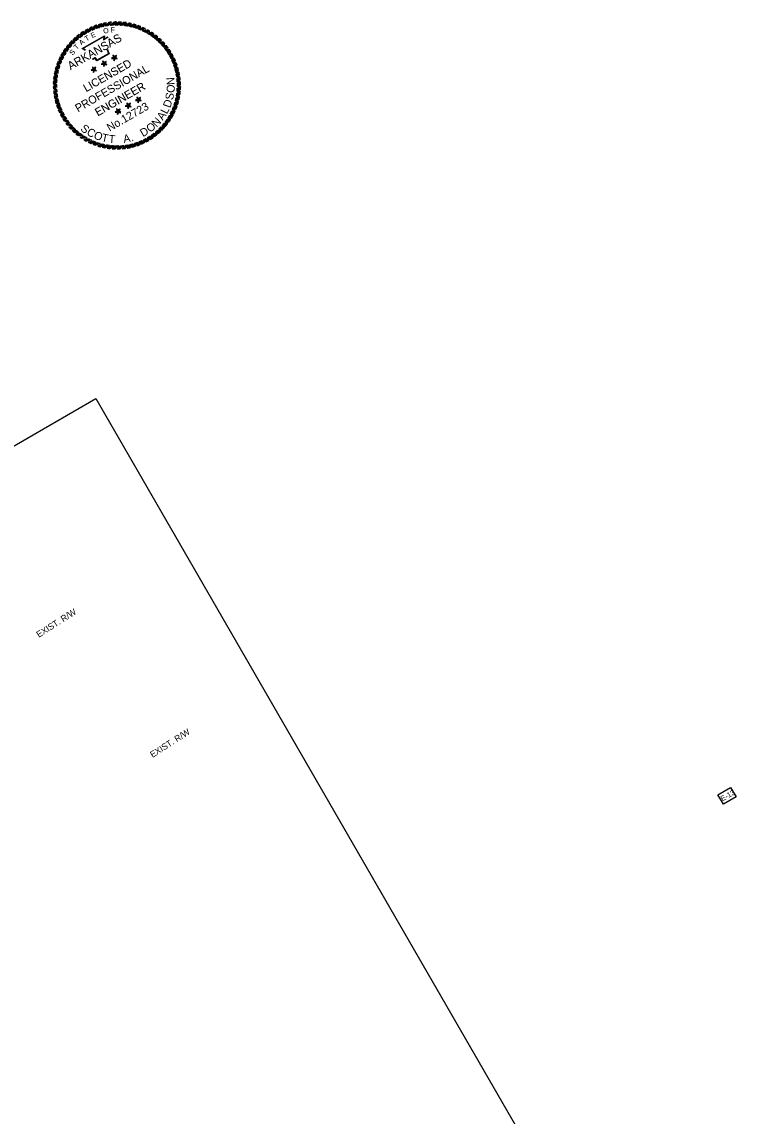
# Model space of a CAD drawing. Extents: x 1293524 to 1295623, y 222963 to 224839.
# Drawn here: x 1294941 to 1295623, y 223794 to 224839 of the extents above; entities that cross this region are included whole.
import ezdxf

# ---------------------------------------------------------------- set-up
doc = ezdxf.new("R2010")
doc.units = 0
for name, color, linetype in [('1', 7, 'Continuous'), ('10Tan10', 7, 'Continuous'), ('Default', 7, 'Continuous'), ('G-No Plot-Border-1', 7, 'Continuous')]:
    doc.layers.add(name, color=color, linetype=linetype)

# ---------------------------------------------------------------- blocks, each defined once
blk = doc.blocks.new('STAR')
at = {"layer": 'Default'}
for p, q in [((0.059, 0.019), (-0.059, 0.019)), ((-0.059, 0.019), (0.036, -0.05)), ((0, 0.062), (-0.037, -0.05)), ((-0.036, -0.05), (0.059, 0.019)), ((-0.008, 0), (0.009, 0)), ((0.036, -0.05), (0, 0.062)), ((0, 0.006), (0, -0.008))]:
    blk.add_line(p, q, dxfattribs=at)
blk = doc.blocks.new('RP')
at = {"layer": 'Default'}
for p, q in [((-0.078, 1.266), (0.003, 1.33)), ((-0.058, 1.267), (0.022, 1.33)), ((-0.038, 1.267), (0.04, 1.329)), ((-0.018, 1.268), (0.059, 1.329))]:
    blk.add_line(p, q, dxfattribs=at)
for radius, start, end in [(1.268, 90.7933, 93.5307), (1.33, 87.4562, 89.8699)]:
    blk.add_arc((0, 0), radius, start, end, dxfattribs=at)

msp = doc.modelspace()

# ---------------------------------------------------------------- linework, layer by layer
at = {"layer": '1'}
msp.add_lwpolyline([(1295606, 224100.5), (1295618.2, 224107.5), (1295623.4, 224098.4), (1295611.3, 224091.4)], close=True, dxfattribs=at)
at = {"layer": 'Default'}
for points in [[(1295001.4, 224811.3), (1294998.6, 224813.3), (1295019.9, 224825.5), (1295019.4, 224822.3), (1295020.8, 224823.1), (1295022, 224823.8), (1295023.3, 224824.4)], [(1295001.4, 224811.4), (1294998.7, 224813.3), (1295020, 224825.5), (1295019.5, 224822.3), (1295020.9, 224823.1), (1295022.1, 224823.8), (1295023.4, 224824.4)], [(1295001.7, 224811.7), (1294999.4, 224813.3), (1295019.5, 224824.8), (1295019, 224821.5), (1295021.1, 224822.8), (1295022.3, 224823.5), (1295023.5, 224824)], [(1295001.6, 224811.6), (1294999.4, 224813.2), (1295019.4, 224824.8), (1295018.9, 224821.5), (1295021, 224822.8), (1295022.2, 224823.5), (1295023.5, 224824.1)], [(1295023.2, 224812), (1295023, 224811.5), (1295023.2, 224811), (1295023.7, 224809.9), (1295024.5, 224808.4), (1295012.7, 224801.5), (1295011.5, 224803.5), (1295011.3, 224804), (1295010.7, 224803.8), (1295009, 224802.9), (1295008.4, 224803.1)], [(1295023.2, 224812), (1295023.1, 224811.5), (1295023.2, 224811), (1295023.7, 224809.8), (1295024.5, 224808.3), (1295012.7, 224801.5), (1295011.5, 224803.5), (1295011.3, 224804), (1295010.7, 224803.8), (1295009, 224802.9), (1295008.5, 224803.2)], [(1295022.8, 224812.2), (1295022.6, 224811.6), (1295022.8, 224810.9), (1295023.3, 224809.7), (1295024, 224808.5), (1295012.8, 224802.1), (1295011.9, 224803.7), (1295011.5, 224804.4), (1295010.6, 224804.2), (1295009, 224803.3), (1295008.6, 224803.5)], [(1295022.9, 224812.1), (1295022.6, 224811.5), (1295022.8, 224810.9), (1295023.3, 224809.6), (1295024, 224808.5), (1295012.8, 224802.1), (1295011.9, 224803.7), (1295011.5, 224804.4), (1295010.6, 224804.2), (1295009, 224803.3), (1295008.6, 224803.5)]]:
    msp.add_lwpolyline(points, dxfattribs=at)
at = {"layer": 'G-No Plot-Border-1'}
msp.add_lwpolyline([(1294045, 222962.9), (1293523.9, 223865.5), (1294561.4, 224464.5), (1294586.2, 224421.6), (1294757.9, 224520.8), (1294765.6, 224507.3), (1294827.6, 224543.1), (1294901.4, 224415.4), (1295011.8, 224479.1), (1295426.7, 223760.5)], close=True, dxfattribs=at)
msp.add_lwpolyline([(1294045, 222962.9), (1293523.9, 223865.5), (1294561.4, 224464.5), (1294586.2, 224421.6), (1294757.9, 224520.8), (1294765.6, 224507.3), (1294827.6, 224543.1), (1294901.4, 224415.4), (1295011.8, 224479.1), (1295426.7, 223760.5)], close=True, dxfattribs=at)
msp.add_lwpolyline([(1294045, 222962.9), (1293523.9, 223865.5), (1294561.4, 224464.5), (1294586.2, 224421.6), (1294757.9, 224520.8), (1294765.6, 224507.3), (1294827.6, 224543.1), (1294901.4, 224415.4), (1295011.8, 224479.1), (1295426.7, 223760.5)], close=True, dxfattribs=at)
msp.add_lwpolyline([(1294045, 222962.9), (1293523.9, 223865.5), (1294561.4, 224464.5), (1294586.2, 224421.6), (1294757.9, 224520.8), (1294765.6, 224507.3), (1294827.6, 224543.1), (1294901.4, 224415.4), (1295011.8, 224479.1), (1295426.7, 223760.5)], close=True, dxfattribs=at)

# ---------------------------------------------------------------- block references
at = {"layer": 'Default'}
for name, p, xscale, yscale, rotation in [('RP', (1295031.9, 224778), 45.58827671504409, 45.58827671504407, 12.000000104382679), ('RP', (1295031.8, 224777.9), 45.58827671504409, 45.58827671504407, 11.804199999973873), ('RP', (1295031.9, 224778), 45.58827671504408, 45.58827671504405, 7.500000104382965), ('RP', (1295031.8, 224777.9), 45.58827671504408, 45.58827671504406, 7.3041999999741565), ('RP', (1295031.9, 224778), 45.58827671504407, 45.58827671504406, 3.000000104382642), ('RP', (1295031.8, 224777.9), 45.58827671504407, 45.58827671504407, 2.804199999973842), ('RP', (1295031.9, 224778), 45.58827671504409, 45.588276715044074, -1.4999998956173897), ('RP', (1295031.8, 224777.9), 45.588276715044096, 45.58827671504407, -1.6958000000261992), ('RP', (1295031.9, 224778), 45.58827671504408, 45.58827671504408, -5.999999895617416), ('RP', (1295031.8, 224777.9), 45.58827671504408, 45.588276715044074, -6.195800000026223), ('RP', (1295031.9, 224778), 45.58827671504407, 45.588276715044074, -10.49999989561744), ('RP', (1295031.8, 224777.9), 45.588276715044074, 45.58827671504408, -10.695800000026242), ('RP', (1295031.9, 224778), 45.58827671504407, 45.58827671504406, -14.999999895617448), ('RP', (1295031.8, 224777.9), 45.58827671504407, 45.58827671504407, -15.19580000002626), ('RP', (1295031.9, 224778), 45.588276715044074, 45.58827671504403, 39.00000010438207), ('RP', (1295031.8, 224777.9), 45.58827671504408, 45.58827671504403, 38.80419999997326), ('RP', (1295031.9, 224778), 45.588276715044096, 45.588276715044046, 34.500000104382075), ('RP', (1295031.8, 224777.9), 45.588276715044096, 45.58827671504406, 34.304199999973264), ('RP', (1295031.9, 224778), 45.588276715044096, 45.588276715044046, 30.00000010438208), ('RP', (1295031.8, 224777.9), 45.58827671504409, 45.588276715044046, 29.804199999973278), ('RP', (1295031.9, 224778), 45.58827671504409, 45.588276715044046, 25.50000010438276), ('RP', (1295031.8, 224777.9), 45.588276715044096, 45.58827671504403, 25.304199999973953), ('RP', (1295031.9, 224778), 45.588276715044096, 45.58827671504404, 21.00000010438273), ('RP', (1295031.8, 224777.9), 45.58827671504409, 45.588276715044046, 20.804199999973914), ('RP', (1295031.9, 224778), 45.588276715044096, 45.58827671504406, 16.50000010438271), ('RP', (1295031.8, 224777.9), 45.58827671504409, 45.58827671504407, 16.304199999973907), ('RP', (1295031.9, 224778), 45.58827671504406, 45.58827671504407, -19.499999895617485), ('RP', (1295031.8, 224777.9), 45.58827671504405, 45.58827671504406, -19.695800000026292), ('RP', (1295031.9, 224778), 45.58827671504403, 45.58827671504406, -23.999999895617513), ('RP', (1295031.8, 224777.9), 45.58827671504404, 45.58827671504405, -24.19580000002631), ('RP', (1295031.9, 224778), 45.58827671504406, 45.58827671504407, -28.499999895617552), ('RP', (1295031.8, 224777.9), 45.58827671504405, 45.58827671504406, -28.69580000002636), ('RP', (1295031.9, 224778), 45.588276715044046, 45.58827671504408, -32.99999989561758), ('RP', (1295031.8, 224777.9), 45.58827671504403, 45.58827671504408, -33.19580000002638), ('RP', (1295031.9, 224778), 45.58827671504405, 45.58827671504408, -37.49999989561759), ('RP', (1295031.8, 224777.9), 45.58827671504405, 45.58827671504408, -37.695800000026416), ('RP', (1295031.9, 224778), 45.588276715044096, 45.58827671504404, 52.50000010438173), ('RP', (1295031.8, 224777.9), 45.58827671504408, 45.58827671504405, 52.30419999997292), ('RP', (1295031.8, 224777.9), 45.58827671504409, 45.588276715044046, 47.80419999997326), ('RP', (1295031.9, 224778), 45.58827671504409, 45.588276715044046, 48.00000010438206), ('RP', (1295031.8, 224777.9), 45.58827671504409, 45.588276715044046, 43.30419999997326), ('RP', (1295031.9, 224778), 45.58827671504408, 45.588276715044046, 43.50000010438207), ('RP', (1295031.9, 224778), 45.58827671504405, 45.58827671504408, -41.99999989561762), ('RP', (1295031.8, 224777.9), 45.588276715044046, 45.58827671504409, -42.19580000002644), ('RP', (1295031.9, 224778), 45.58827671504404, 45.58827671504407, -46.49999989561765), ('RP', (1295031.8, 224777.9), 45.58827671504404, 45.58827671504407, -46.69580000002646), ('RP', (1295031.9, 224778), 45.588276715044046, 45.58827671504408, -50.999999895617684), ('RP', (1295031.8, 224777.9), 45.588276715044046, 45.58827671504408, -51.19580000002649), ('RP', (1295031.8, 224777.9), 45.58827671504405, 45.58827671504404, 61.30419999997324), ('RP', (1295031.9, 224778), 45.58827671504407, 45.58827671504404, 61.50000010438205), ('RP', (1295031.8, 224777.9), 45.58827671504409, 45.58827671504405, 56.804199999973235), ('RP', (1295031.9, 224778), 45.58827671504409, 45.58827671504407, 57.000000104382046), ('STAR', (1295029.4, 224804.5), 45.588276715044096, 45.588276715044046, 30.00000010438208), ('STAR', (1295029.4, 224804.4), 45.58827671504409, 45.588276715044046, 29.804199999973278), ('RP', (1295031.9, 224778), 45.588276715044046, 45.58827671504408, -55.499999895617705), ('RP', (1295031.8, 224777.9), 45.58827671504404, 45.588276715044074, -55.695800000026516), ('RP', (1295031.9, 224778), 45.588276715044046, 45.588276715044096, -59.99999989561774), ('RP', (1295031.8, 224777.9), 45.588276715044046, 45.58827671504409, -60.19580000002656), ('RP', (1295031.9, 224778), 45.58827671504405, 45.58827671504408, -64.49999989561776), ('RP', (1295031.8, 224777.9), 45.588276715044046, 45.58827671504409, -64.69580000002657), ('RP', (1295031.8, 224777.9), 45.58827671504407, 45.58827671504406, 74.80419999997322), ('RP', (1295031.9, 224778), 45.588276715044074, 45.58827671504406, 75.00000010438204), ('RP', (1295031.8, 224777.9), 45.588276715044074, 45.58827671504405, 70.30419999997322), ('RP', (1295031.9, 224778), 45.588276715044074, 45.58827671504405, 70.50000010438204), ('RP', (1295031.8, 224777.9), 45.58827671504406, 45.58827671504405, 65.80419999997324), ('RP', (1295031.9, 224778), 45.588276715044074, 45.58827671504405, 66.00000010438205), ('STAR', (1295009.9, 224793.2), 45.58827671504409, 45.588276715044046, 29.804199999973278), ('STAR', (1295009.9, 224793.2), 45.588276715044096, 45.588276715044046, 30.00000010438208), ('STAR', (1295019.6, 224798.8), 45.58827671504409, 45.588276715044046, 29.804199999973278), ('STAR', (1295019.7, 224798.9), 45.588276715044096, 45.588276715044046, 30.00000010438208), ('RP', (1295031.9, 224778), 45.58827671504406, 45.58827671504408, -68.9999998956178), ('RP', (1295031.8, 224777.9), 45.58827671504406, 45.588276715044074, -69.19580000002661), ('RP', (1295031.9, 224778), 45.58827671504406, 45.588276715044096, -73.49999989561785), ('RP', (1295031.8, 224777.9), 45.58827671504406, 45.588276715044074, -73.69580000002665), ('RP', (1295031.8, 224777.9), 45.588276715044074, 45.58827671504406, 83.80419999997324), ('RP', (1295031.9, 224778), 45.588276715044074, 45.58827671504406, 84.00000010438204), ('RP', (1295031.8, 224777.9), 45.58827671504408, 45.58827671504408, 79.30419999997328), ('RP', (1295031.9, 224778), 45.58827671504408, 45.588276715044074, 79.50000010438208), ('RP', (1295031.9, 224778), 45.58827671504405, 45.588276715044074, -77.99999989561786), ('RP', (1295031.8, 224777.9), 45.588276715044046, 45.58827671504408, -78.19580000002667), ('RP', (1295031.9, 224778), 45.588276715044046, 45.58827671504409, -82.49999989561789), ('RP', (1295031.8, 224777.9), 45.58827671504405, 45.58827671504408, -82.6958000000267), ('RP', (1295031.8, 224777.9), 45.58827671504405, 45.58827671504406, 88.30419999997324), ('RP', (1295031.8, 224777.9), 45.58827671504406, 45.58827671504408, 92.80419999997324), ('RP', (1295031.9, 224778), 45.58827671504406, 45.58827671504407, 88.50000010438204), ('RP', (1295031.9, 224778), 45.58827671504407, 45.58827671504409, 93.00000010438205), ('RP', (1295031.8, 224777.9), 45.588276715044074, 45.58827671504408, -96.19580000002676), ('RP', (1295031.9, 224778), 45.588276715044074, 45.58827671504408, -95.99999989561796), ('RP', (1295031.9, 224778), 45.588276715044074, 45.58827671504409, -86.99999989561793), ('RP', (1295031.8, 224777.9), 45.58827671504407, 45.58827671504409, -87.19580000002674), ('RP', (1295031.8, 224777.9), 45.58827671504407, 45.588276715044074, -91.69580000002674), ('RP', (1295031.9, 224778), 45.58827671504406, 45.58827671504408, -91.49999989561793), ('RP', (1295031.8, 224777.9), 45.58827671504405, 45.58827671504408, 97.30419999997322), ('RP', (1295031.9, 224778), 45.58827671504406, 45.58827671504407, 97.50000010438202), ('RP', (1295031.8, 224777.9), 45.58827671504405, 45.58827671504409, 101.80419999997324), ('RP', (1295031.9, 224778), 45.58827671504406, 45.588276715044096, 102.00000010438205), ('RP', (1295031.8, 224777.9), 45.58827671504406, 45.58827671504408, 106.30419999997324), ('RP', (1295031.9, 224778), 45.58827671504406, 45.588276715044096, 106.50000010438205), ('STAR', (1295052.4, 224764.3), 45.58827671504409, 45.588276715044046, 29.804199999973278), ('STAR', (1295052.5, 224764.4), 45.588276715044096, 45.588276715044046, 30.00000010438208), ('RP', (1295031.8, 224777.9), 45.58827671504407, 45.58827671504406, -105.19580000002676), ('RP', (1295031.9, 224778), 45.588276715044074, 45.58827671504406, -104.99999989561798), ('RP', (1295031.8, 224777.9), 45.588276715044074, 45.58827671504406, -100.69580000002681), ('RP', (1295031.9, 224778), 45.588276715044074, 45.58827671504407, -100.49999989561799), ('RP', (1295031.8, 224777.9), 45.58827671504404, 45.588276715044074, 110.80419999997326), ('RP', (1295031.9, 224778), 45.588276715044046, 45.58827671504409, 111.00000010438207), ('RP', (1295031.8, 224777.9), 45.588276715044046, 45.588276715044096, 115.30419999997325), ('RP', (1295031.9, 224778), 45.58827671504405, 45.58827671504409, 115.50000010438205), ('STAR', (1295032.8, 224753.1), 45.58827671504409, 45.588276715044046, 29.804199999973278), ('STAR', (1295033, 224753.2), 45.588276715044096, 45.588276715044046, 30.00000010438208), ('STAR', (1295042.6, 224758.7), 45.58827671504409, 45.588276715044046, 29.804199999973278), ('STAR', (1295042.8, 224758.8), 45.588276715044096, 45.588276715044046, 30.00000010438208), ('RP', (1295031.9, 224778), 45.588276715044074, 45.58827671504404, -118.49999989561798), ('RP', (1295031.8, 224777.9), 45.58827671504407, 45.58827671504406, -114.19580000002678), ('RP', (1295031.9, 224778), 45.58827671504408, 45.58827671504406, -113.99999989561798), ('RP', (1295031.8, 224777.9), 45.58827671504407, 45.588276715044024, -109.69580000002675), ('RP', (1295031.9, 224778), 45.58827671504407, 45.588276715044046, -109.49999989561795), ('RP', (1295031.8, 224777.9), 45.588276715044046, 45.588276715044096, 119.80419999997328), ('RP', (1295031.9, 224778), 45.58827671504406, 45.5882767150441, 120.00000010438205), ('RP', (1295031.8, 224777.9), 45.58827671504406, 45.58827671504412, 124.30419999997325), ('RP', (1295031.9, 224778), 45.58827671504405, 45.5882767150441, 124.50000010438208), ('RP', (1295031.8, 224777.9), 45.58827671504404, 45.58827671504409, 128.8041999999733), ('RP', (1295031.9, 224778), 45.58827671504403, 45.58827671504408, 129.0000001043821), ('RP', (1295031.8, 224777.9), 45.58827671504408, 45.58827671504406, -127.6958000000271), ('RP', (1295031.9, 224778), 45.58827671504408, 45.58827671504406, -127.4999998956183), ('RP', (1295031.8, 224777.9), 45.588276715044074, 45.58827671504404, -123.1958000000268), ('RP', (1295031.9, 224778), 45.588276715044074, 45.58827671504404, -122.99999989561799), ('RP', (1295031.8, 224777.9), 45.58827671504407, 45.588276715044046, -118.69580000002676), ('RP', (1295031.8, 224777.9), 45.58827671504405, 45.58827671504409, 133.30419999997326), ('RP', (1295031.9, 224778), 45.58827671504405, 45.58827671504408, 133.50000010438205), ('RP', (1295031.8, 224777.9), 45.58827671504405, 45.5882767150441, 137.8041999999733), ('RP', (1295031.9, 224778), 45.58827671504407, 45.588276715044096, 138.00000010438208), ('RP', (1295031.8, 224777.9), 45.588276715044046, 45.58827671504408, 142.3041999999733), ('RP', (1295031.9, 224778), 45.58827671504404, 45.588276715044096, 142.50000010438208), ('RP', (1295031.8, 224777.9), 45.588276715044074, 45.58827671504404, -141.19580000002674), ('RP', (1295031.9, 224778), 45.588276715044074, 45.58827671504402, -140.99999989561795), ('RP', (1295031.8, 224777.9), 45.58827671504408, 45.588276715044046, -136.69580000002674), ('RP', (1295031.9, 224778), 45.58827671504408, 45.58827671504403, -136.49999989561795), ('RP', (1295031.8, 224777.9), 45.58827671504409, 45.588276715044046, -132.19580000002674), ('RP', (1295031.9, 224778), 45.588276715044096, 45.588276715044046, -131.99999989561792), ('RP', (1295031.8, 224777.9), 45.58827671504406, 45.58827671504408, 146.8041999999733), ('RP', (1295031.9, 224778), 45.58827671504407, 45.58827671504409, 147.00000010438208), ('RP', (1295031.8, 224777.9), 45.58827671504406, 45.58827671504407, 151.3041999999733), ('RP', (1295031.9, 224778), 45.58827671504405, 45.588276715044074, 151.50000010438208), ('RP', (1295031.8, 224777.9), 45.588276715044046, 45.58827671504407, 155.8041999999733), ('RP', (1295031.9, 224778), 45.588276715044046, 45.58827671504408, 156.0000001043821), ('RP', (1295031.8, 224777.9), 45.58827671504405, 45.588276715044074, 160.3041999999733), ('RP', (1295031.9, 224778), 45.58827671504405, 45.588276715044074, 160.50000010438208), ('RP', (1295031.8, 224777.9), 45.58827671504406, 45.58827671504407, 164.8041999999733), ('RP', (1295031.9, 224778), 45.58827671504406, 45.588276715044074, 165.0000001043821), ('RP', (1295031.9, 224778), 45.5882767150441, 45.58827671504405, -167.99999989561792), ('RP', (1295031.8, 224777.9), 45.58827671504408, 45.58827671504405, -163.69580000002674), ('RP', (1295031.9, 224778), 45.58827671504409, 45.588276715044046, -163.49999989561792), ('RP', (1295031.8, 224777.9), 45.58827671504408, 45.58827671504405, -159.1958000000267), ('RP', (1295031.9, 224778), 45.58827671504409, 45.588276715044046, -158.99999989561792), ('RP', (1295031.8, 224777.9), 45.588276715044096, 45.588276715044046, -154.6958000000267), ('RP', (1295031.9, 224778), 45.5882767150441, 45.58827671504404, -154.49999989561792), ('RP', (1295031.8, 224777.9), 45.588276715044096, 45.588276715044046, -150.19580000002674), ('RP', (1295031.9, 224778), 45.5882767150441, 45.58827671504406, -149.99999989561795), ('RP', (1295031.8, 224777.9), 45.58827671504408, 45.588276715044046, -145.69580000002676), ('RP', (1295031.9, 224778), 45.588276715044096, 45.58827671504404, -145.49999989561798), ('RP', (1295031.8, 224777.9), 45.588276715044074, 45.58827671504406, 169.30419999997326), ('RP', (1295031.9, 224778), 45.58827671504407, 45.588276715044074, 169.50000010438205), ('RP', (1295031.8, 224777.9), 45.588276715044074, 45.58827671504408, 173.8041999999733), ('RP', (1295031.9, 224778), 45.58827671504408, 45.588276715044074, 174.00000010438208), ('RP', (1295031.8, 224777.9), 45.58827671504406, 45.58827671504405, 178.3041999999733), ('RP', (1295031.9, 224778), 45.58827671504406, 45.58827671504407, 178.50000010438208), ('RP', (1295031.8, 224777.9), 45.58827671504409, 45.588276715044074, -177.1958000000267), ('RP', (1295031.9, 224778), 45.5882767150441, 45.58827671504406, -176.99999989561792), ('RP', (1295031.8, 224777.9), 45.588276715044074, 45.58827671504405, -172.6958000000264), ('RP', (1295031.9, 224778), 45.588276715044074, 45.58827671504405, -172.49999989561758), ('RP', (1295031.8, 224777.9), 45.588276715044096, 45.58827671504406, -168.19580000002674)]:
    msp.add_blockref(name, p, dxfattribs=dict(at, xscale=xscale, yscale=yscale, rotation=rotation))

# ---------------------------------------------------------------- texts
at = {"layer": '1'}
msp.add_text('E-13', height=5, rotation=29.6136, dxfattribs=at).set_placement((1295610.3, 224094))
at = {"layer": '10Tan10'}
for p in [(1294957.3, 224250.3), (1295065.9, 224135.6)]:
    msp.add_text('EXIST. R/W', height=6, rotation=32.6554, dxfattribs=at).set_placement(p)
at = {"layer": 'Default'}
for s, height, rotation, p in [('ARKANSAS', 7.89, 29.8042, (1294987.5, 224792.5)), ('ARKANSAS', 7.89, 30, (1294987.5, 224792.4)), ('E', 4.84, 26.672, (1295008.2, 224823)), ('E', 4.84, 26.4762, (1295008.2, 224823)), ('O', 4.84, 11.2218, (1295019.2, 224827.4)), ('O', 4.84, 11.026, (1295019.3, 224827.4)), ('F', 4.84, 5.3628, (1295026.1, 224828.5)), ('F', 4.84, 5.167, (1295026.2, 224828.4)), ('T', 4.84, 46.7057, (1294993.5, 224811.9)), ('T', 4.84, 46.9015, (1294993.5, 224811.8)), ('A', 4.84, 38.6788, (1294997.8, 224816.1)), ('A', 4.84, 38.483, (1294997.9, 224816.1)), ('T', 4.84, 31.4789, (1295002.7, 224820)), ('T', 4.84, 31.2831, (1295002.8, 224820)), ('S', 4.84, 49.7726, (1294989.5, 224806.3)), ('S', 4.84, 49.5768, (1294989.6, 224806.4)), ('PROFESSIONAL', 7.642, 29.8042, (1294994.6, 224752.2)), ('PROFESSIONAL', 7.642, 30, (1294994.7, 224752.1)), ('LICENSED', 7.64, 30, (1295002.5, 224771.4)), ('LICENSED', 7.64, 29.8042, (1295002.4, 224771.4)), ('N', 7.64, 94.5417, (1295087.2, 224778.7)), ('ENGINEER', 7.64, 29.8042, (1295013.5, 224748.3)), ('ENGINEER', 7.64, 30, (1295013.7, 224748.3)), ('O', 7.64, 86.2381, (1295086.8, 224770.7)), ('D', 7.64, 70.3857, (1295082.7, 224756)), ('S', 7.64, 78.6894, (1295085.3, 224763.6)), ('No.12723', 7.61, 30, (1295024.9, 224733.7)), ('L', 7.64, 63.5919, (1295079.8, 224750.1)), ('N', 7.64, 46.9847, (1295069.8, 224737.6)), ('A', 7.64, 56.0431, (1295075.7, 224744.1)), ('S', 7.64, 323.9485, (1294996.4, 224735.4)), ('C', 7.64, 331.4973, (1295002.3, 224731.2)), ('O', 7.64, 339.4235, (1295009.1, 224727.5)), ('D', 7.64, 30.3774, (1295056.7, 224728.5)), ('O', 7.64, 38.681, (1295063.6, 224732.6)), ('T', 7.64, 347.7271, (1295016.6, 224724.8)), ('T', 7.64, 355.2758, (1295023.7, 224723.2)), ('A', 7.64, 10.7507, (1295038.6, 224723)), ('.', 7.64, 18.2995, (1295045.8, 224724.4))]:
    msp.add_text(s, height=height, rotation=rotation, dxfattribs=at).set_placement(p)

doc.saveas('drawing.dxf')
